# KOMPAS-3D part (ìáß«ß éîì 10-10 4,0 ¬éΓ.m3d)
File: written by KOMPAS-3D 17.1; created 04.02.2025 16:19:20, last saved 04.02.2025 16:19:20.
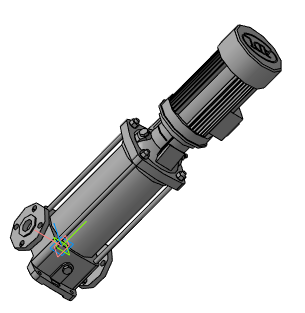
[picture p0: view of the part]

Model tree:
1. Операция без истории:1  (labels: Насос ВМН 10-10 4,0 кВт)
